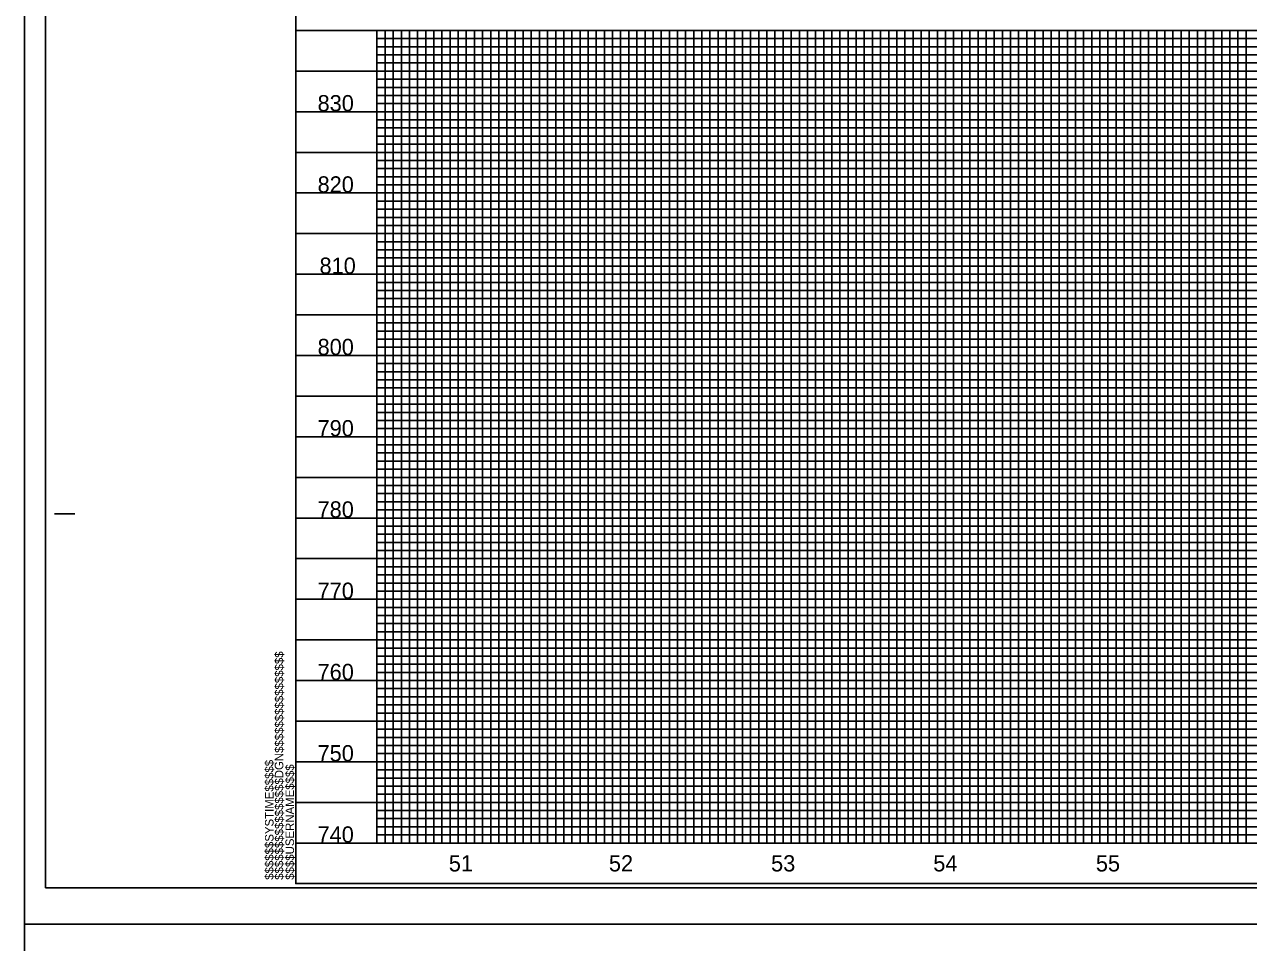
# Model space of a CAD drawing. Extents: x 1755181 to 1757273, y 729911 to 735411.
# Drawn here: x 1755181 to 1755934, y 733200 to 733764 of the extents above; entities that cross this region are included whole.
import ezdxf

# ---------------------------------------------------------------- set-up
doc = ezdxf.new("R2010")
doc.units = 0
for name, color, linetype in [('Exist Vertical Profile Horizontal Axis Label Major', 7, 'Continuous'), ('Exist Vertical Profile Vertical Axis Label', 7, 'Continuous'), ('Scratch_Level_3', 7, 'Continuous'), ('Sheet Cutting Line CELL', 7, 'Continuous'), ('Sheet DOT Grid CELL', 7, 'Continuous'), ('Sheet Plot Border Inside CELL', 7, 'Continuous'), ('Sheet Plot Border Outside CELL', 7, 'Continuous'), ('Sheet Profile CELL', 7, 'Continuous'), ('Sheet Profile Grid Major CELL', 7, 'Continuous'), ('Sheet Profile Grid Middle CELL', 7, 'Continuous'), ('Sheet Profile Grid Minor CELL', 7, 'Continuous')]:
    doc.layers.add(name, color=color, linetype=linetype)

msp = doc.modelspace()

# ---------------------------------------------------------------- linework, layer by layer
at = {"layer": 'Scratch_Level_3'}
msp.add_lwpolyline([(1755397.67, 733760.78), (1756847.67, 733760.78), (1756847.67, 733260.78), (1755397.67, 733260.78)], close=True, dxfattribs=at)
at = {"layer": 'Sheet Cutting Line CELL'}
for p, q in [((1755180.67, 734310.78), (1755180.67, 733210.78)), ((1755180.67, 733210.78), (1756864.67, 733210.78)), ((1755180.67, 733210.78), (1755180.67, 732110.78))]:
    msp.add_line(p, q, dxfattribs=at)
at = {"layer": 'Sheet DOT Grid CELL'}
for p, q in [((1755347.67, 733760.78), (1756797.67, 733760.78)), ((1755397.67, 733760.78), (1755397.67, 733260.78)), ((1755447.67, 733760.78), (1755447.67, 733260.78)), ((1755497.67, 733760.78), (1755497.67, 733260.78)), ((1755547.67, 733760.78), (1755547.67, 733260.78)), ((1755597.67, 733760.78), (1755597.67, 733260.78)), ((1755647.67, 733760.78), (1755647.67, 733260.78)), ((1755697.67, 733760.78), (1755697.67, 733260.78)), ((1755747.67, 733760.78), (1755747.67, 733260.78)), ((1755797.67, 733760.78), (1755797.67, 733260.78)), ((1755847.67, 733760.78), (1755847.67, 733260.78)), ((1755897.67, 733760.78), (1755897.67, 733260.78)), ((1755347.67, 733710.78), (1756847.56, 733710.78)), ((1755347.67, 733660.78), (1756847.56, 733660.78)), ((1755347.67, 733610.78), (1756847.56, 733610.78)), ((1755347.67, 733560.78), (1756847.56, 733560.78)), ((1755347.67, 733510.78), (1756847.56, 733510.78)), ((1755347.67, 733460.78), (1756847.56, 733460.78)), ((1755347.67, 733410.78), (1756847.56, 733410.78)), ((1755347.67, 733360.78), (1756847.56, 733360.78)), ((1755347.67, 733310.78), (1756847.56, 733310.78))]:
    msp.add_line(p, q, dxfattribs=at)
at = {"layer": 'Sheet Plot Border Inside CELL'}
msp.add_lwpolyline([(1755193.67, 733233.23), (1756860.17, 733233.23), (1756860.17, 734288.33), (1755193.67, 734288.33)], close=True, dxfattribs=at)
at = {"layer": 'Sheet Plot Border Outside CELL'}
for points in [[(1755180.67, 733210.78), (1756864.67, 733210.78), (1756864.67, 734310.78), (1755180.67, 734310.78)], [(1755180.67, 732110.78), (1756864.67, 732110.78), (1756864.67, 733210.78), (1755180.67, 733210.78)]]:
    msp.add_lwpolyline(points, close=True, dxfattribs=at)
at = {"layer": 'Sheet Profile CELL'}
for p, q in [((1755347.67, 733760.78), (1756847.67, 733760.78)), ((1755199.17, 733463.28), (1755211.67, 733463.28)), ((1756847.67, 733260.78), (1755347.67, 733260.78)), ((1755347.67, 733235.78), (1756847.67, 733235.78)), ((1755347.67, 733235.78), (1755347.67, 733235.78))]:
    msp.add_line(p, q, dxfattribs=at)
msp.add_lwpolyline([(1756847.67, 734285.78), (1755347.67, 734285.78), (1755347.67, 733235.78), (1756847.67, 733235.78)], close=True, dxfattribs=at)
msp.add_lwpolyline([(1755385.17, 733235.78), (1755385.17, 733235.78)], dxfattribs=at)
at = {"layer": 'Sheet Profile Grid Major CELL'}
msp.add_line((1755847.67, 733760.78), (1755897.67, 733760.78), dxfattribs=at)
for points in [[(1755397.67, 733760.78), (1755397.67, 733260.78), (1755447.67, 733260.78), (1755447.67, 733760.78), (1755497.67, 733760.78), (1755497.67, 733260.78), (1755547.67, 733260.78), (1755547.67, 733760.78), (1755597.67, 733760.78), (1755597.67, 733260.78), (1755647.67, 733260.78), (1755647.67, 733760.78), (1755697.67, 733760.78), (1755697.67, 733260.78), (1755747.67, 733260.78), (1755747.67, 733760.78), (1755797.67, 733760.78), (1755797.67, 733260.78), (1755847.67, 733260.78), (1755847.67, 733760.78), (1755897.67, 733760.78), (1755897.67, 733260.78), (1755947.67, 733260.78)], [(1756847.67, 733710.78), (1755347.67, 733710.78)], [(1756847.67, 733660.78), (1755347.67, 733660.78), (1755347.67, 733610.78), (1756847.67, 733610.78)], [(1756847.67, 733560.78), (1755347.67, 733560.78), (1755347.67, 733510.78), (1756847.67, 733510.78)], [(1756847.67, 733460.78), (1755347.67, 733460.78), (1755347.67, 733410.78), (1756847.67, 733410.78)], [(1756847.67, 733360.78), (1755347.67, 733360.78), (1755347.67, 733360.78), (1755347.67, 733310.78), (1756847.67, 733310.78)], [(1756847.67, 733260.78), (1755347.67, 733260.78)]]:
    msp.add_lwpolyline(points, dxfattribs=at)
at = {"layer": 'Sheet Profile Grid Middle CELL'}
for points in [[(1755372.67, 733760.78), (1755422.67, 733760.78), (1755422.67, 733260.78), (1755472.67, 733260.78), (1755472.67, 733760.78), (1755522.67, 733760.78), (1755522.67, 733260.78), (1755572.67, 733260.78), (1755572.67, 733760.78), (1755622.67, 733760.78), (1755622.67, 733260.78), (1755672.67, 733260.78), (1755672.67, 733760.78), (1755722.67, 733760.78), (1755722.67, 733260.78), (1755772.67, 733260.78), (1755772.67, 733760.78), (1755822.67, 733760.78), (1755822.67, 733260.78), (1755872.67, 733260.78), (1755872.67, 733760.78), (1755922.67, 733760.78), (1755922.67, 733260.78), (1755972.67, 733260.78)], [(1755347.67, 733735.78), (1756097.67, 733735.78)], [(1756097.67, 733685.78), (1755347.67, 733685.78), (1755347.67, 733635.78), (1756097.67, 733635.78)], [(1756097.67, 733585.78), (1755347.67, 733585.78), (1755347.67, 733535.78), (1756097.67, 733535.78)], [(1756097.67, 733485.78), (1755347.67, 733485.78), (1755347.67, 733435.78), (1756097.67, 733435.78)], [(1756097.67, 733385.78), (1755347.67, 733385.78), (1755347.67, 733335.78), (1756097.67, 733335.78)], [(1756097.67, 733285.78), (1755347.67, 733285.78)]]:
    msp.add_lwpolyline(points, dxfattribs=at)
at = {"layer": 'Sheet Profile Grid Minor CELL'}
for p, q in [((1755397.67, 733755.78), (1756102.67, 733755.78)), ((1756102.67, 733750.78), (1755397.67, 733750.78)), ((1755397.67, 733745.78), (1756102.67, 733745.78)), ((1756102.67, 733740.78), (1755397.67, 733740.78)), ((1755397.67, 733730.78), (1756102.67, 733730.78)), ((1756102.67, 733725.78), (1755397.67, 733725.78)), ((1755397.67, 733720.78), (1756102.67, 733720.78)), ((1756102.67, 733715.78), (1755397.67, 733715.78)), ((1755397.67, 733705.78), (1756102.67, 733705.78)), ((1756102.67, 733700.78), (1755397.67, 733700.78)), ((1755397.67, 733695.78), (1756102.67, 733695.78)), ((1756102.67, 733690.78), (1755397.67, 733690.78)), ((1755397.67, 733680.78), (1756102.67, 733680.78)), ((1756102.67, 733675.78), (1755397.67, 733675.78)), ((1755397.67, 733670.78), (1756102.67, 733670.78)), ((1756102.67, 733665.78), (1755397.67, 733665.78)), ((1755397.67, 733655.78), (1756102.67, 733655.78)), ((1756102.67, 733650.78), (1755397.67, 733650.78)), ((1755397.67, 733645.78), (1756102.67, 733645.78)), ((1756102.67, 733640.78), (1755397.67, 733640.78)), ((1755397.67, 733630.78), (1756102.67, 733630.78)), ((1756102.67, 733625.78), (1755397.67, 733625.78)), ((1755397.67, 733620.78), (1756102.67, 733620.78)), ((1756102.67, 733615.78), (1755397.67, 733615.78)), ((1755397.67, 733605.78), (1756102.67, 733605.78)), ((1756102.67, 733600.78), (1755397.67, 733600.78)), ((1755397.67, 733595.78), (1756102.67, 733595.78)), ((1756102.67, 733590.78), (1755397.67, 733590.78)), ((1755397.67, 733580.78), (1756102.67, 733580.78)), ((1756102.67, 733575.78), (1755397.67, 733575.78)), ((1755397.67, 733570.78), (1756102.67, 733570.78)), ((1756102.67, 733565.86), (1755397.67, 733565.93)), ((1755397.67, 733555.78), (1756102.67, 733555.78)), ((1756102.67, 733550.78), (1755397.67, 733550.78)), ((1755397.67, 733545.78), (1756102.67, 733545.78)), ((1756102.67, 733540.78), (1755397.67, 733540.78)), ((1755397.67, 733530.78), (1756102.67, 733530.78)), ((1756102.67, 733525.78), (1755397.67, 733525.78)), ((1755397.67, 733520.78), (1756102.67, 733520.78)), ((1756102.67, 733515.78), (1755397.67, 733515.78)), ((1755397.67, 733505.78), (1756102.67, 733505.78)), ((1756102.67, 733500.78), (1755397.67, 733500.78)), ((1755397.67, 733495.78), (1756102.67, 733495.78)), ((1756102.67, 733490.78), (1755397.67, 733490.78)), ((1755397.67, 733480.78), (1756102.67, 733480.78)), ((1756102.67, 733475.78), (1755397.67, 733475.78)), ((1755397.67, 733470.78), (1756102.67, 733470.78)), ((1756102.67, 733465.78), (1755397.67, 733465.78)), ((1755397.67, 733455.78), (1756102.67, 733455.78)), ((1756102.67, 733450.78), (1755397.67, 733450.78)), ((1755397.67, 733445.78), (1756102.67, 733445.78)), ((1756102.67, 733440.78), (1755397.67, 733440.78)), ((1755397.67, 733430.78), (1756102.67, 733430.78)), ((1756102.67, 733425.78), (1755397.67, 733425.78)), ((1755397.67, 733420.78), (1756102.67, 733420.78)), ((1756102.67, 733415.78), (1755397.67, 733415.78)), ((1755397.67, 733405.78), (1756102.67, 733405.78)), ((1756102.67, 733400.78), (1755397.67, 733400.78)), ((1755397.67, 733395.78), (1756102.67, 733395.78)), ((1756102.67, 733390.78), (1755397.67, 733390.78)), ((1755397.67, 733380.78), (1756102.67, 733380.78)), ((1756102.67, 733375.78), (1755397.67, 733375.78)), ((1755397.67, 733370.78), (1756102.67, 733370.78)), ((1756102.67, 733365.78), (1755397.67, 733365.78)), ((1755397.67, 733355.78), (1756102.67, 733355.78)), ((1756102.67, 733350.78), (1755397.67, 733350.78)), ((1755397.67, 733345.78), (1756102.67, 733345.78)), ((1756102.67, 733340.78), (1755397.67, 733340.78)), ((1755397.67, 733330.78), (1756102.67, 733330.78)), ((1756102.67, 733325.78), (1755397.67, 733325.78)), ((1755397.67, 733320.78), (1756102.67, 733320.78)), ((1756102.67, 733315.78), (1755397.67, 733315.78)), ((1755397.67, 733305.78), (1756102.67, 733305.78)), ((1756102.67, 733300.78), (1755397.67, 733300.78)), ((1755397.67, 733295.78), (1756102.67, 733295.78)), ((1756102.67, 733290.78), (1755397.67, 733290.78)), ((1755397.67, 733280.78), (1756102.67, 733280.78)), ((1756102.67, 733275.78), (1755397.67, 733275.78)), ((1755397.67, 733270.78), (1756102.67, 733270.78)), ((1755397.67, 733265.78), (1756102.67, 733265.78))]:
    msp.add_line(p, q, dxfattribs=at)
for points in [[(1755397.67, 733760.78), (1755402.67, 733760.78), (1755402.67, 733260.78), (1755407.67, 733260.78), (1755407.67, 733760.78), (1755412.67, 733760.78), (1755412.67, 733260.78), (1755417.67, 733260.78), (1755417.67, 733760.78), (1755427.67, 733760.78), (1755427.67, 733260.78), (1755432.67, 733260.78), (1755432.67, 733760.78), (1755437.67, 733760.78), (1755437.67, 733260.78), (1755442.67, 733260.78), (1755452.67, 733260.78), (1755457.67, 733260.78), (1755457.67, 733760.78), (1755462.67, 733760.78), (1755462.67, 733260.78), (1755467.67, 733260.78), (1755467.67, 733760.78), (1755477.67, 733760.78), (1755477.67, 733260.78), (1755482.67, 733260.78), (1755482.67, 733760.78), (1755487.67, 733760.78), (1755487.67, 733260.78), (1755492.67, 733260.78), (1755492.67, 733760.78), (1755502.67, 733760.78), (1755502.67, 733260.78), (1755507.67, 733260.78), (1755507.67, 733760.78), (1755512.67, 733760.78), (1755512.67, 733260.78), (1755517.67, 733260.78), (1755517.67, 733760.78), (1755527.67, 733760.78), (1755527.67, 733260.78), (1755532.67, 733260.78), (1755532.67, 733760.78), (1755537.67, 733760.78), (1755537.67, 733260.78), (1755542.67, 733260.78), (1755542.67, 733760.78), (1755552.67, 733760.78), (1755552.67, 733260.78), (1755557.67, 733260.78), (1755557.67, 733760.78), (1755562.67, 733760.78), (1755562.67, 733260.78), (1755567.67, 733260.78), (1755567.67, 733760.78), (1755577.67, 733760.78), (1755577.67, 733260.78), (1755582.67, 733260.78), (1755582.67, 733760.78), (1755587.67, 733760.78), (1755587.67, 733260.78), (1755592.67, 733260.78), (1755592.67, 733760.78), (1755602.67, 733760.78), (1755602.67, 733260.78), (1755607.67, 733260.78), (1755607.67, 733760.78), (1755612.67, 733760.78), (1755612.67, 733260.78)], [(1755442.67, 733260.78), (1755442.67, 733760.78), (1755452.67, 733760.78), (1755452.67, 733260.78)], [(1755612.67, 733260.78), (1755617.67, 733260.78), (1755617.67, 733760.78), (1755627.67, 733760.78), (1755627.67, 733260.78), (1755632.67, 733260.78), (1755632.67, 733760.78), (1755637.67, 733760.78), (1755637.67, 733260.78), (1755642.67, 733260.78), (1755642.67, 733760.78), (1755652.67, 733760.78), (1755652.67, 733260.78), (1755657.67, 733260.78), (1755657.67, 733760.78), (1755662.67, 733760.78), (1755662.67, 733260.78), (1755667.67, 733260.78), (1755667.67, 733760.78), (1755677.67, 733760.78), (1755677.67, 733260.78), (1755682.67, 733260.78), (1755682.67, 733760.78), (1755687.67, 733760.78), (1755687.67, 733260.78), (1755692.67, 733260.78), (1755692.67, 733760.78), (1755702.67, 733760.78), (1755702.67, 733260.78), (1755707.67, 733260.78), (1755707.67, 733760.78), (1755712.67, 733760.78), (1755712.67, 733260.78), (1755717.67, 733260.78), (1755717.67, 733760.78), (1755727.67, 733760.78), (1755727.67, 733260.78), (1755732.67, 733260.78), (1755732.67, 733760.78), (1755737.67, 733760.78), (1755737.67, 733260.78), (1755742.67, 733260.78), (1755742.67, 733760.78), (1755752.67, 733760.78), (1755752.67, 733260.78), (1755757.67, 733260.78), (1755757.67, 733760.78), (1755762.67, 733760.78), (1755762.67, 733260.78), (1755767.67, 733260.78), (1755767.67, 733760.78), (1755777.67, 733760.78), (1755777.67, 733260.78), (1755782.67, 733260.78), (1755782.67, 733760.78), (1755787.67, 733760.78), (1755787.67, 733260.78), (1755792.67, 733260.78), (1755792.67, 733760.78), (1755802.67, 733760.78), (1755802.67, 733260.78), (1755807.67, 733260.78), (1755807.67, 733760.78), (1755812.67, 733760.78), (1755812.67, 733260.78), (1755817.67, 733260.78), (1755817.67, 733760.78), (1755827.67, 733760.78), (1755827.67, 733260.78), (1755832.67, 733260.78), (1755832.67, 733760.78), (1755837.67, 733760.78), (1755837.67, 733260.78), (1755842.67, 733260.78), (1755842.67, 733760.78), (1755852.67, 733760.78), (1755852.67, 733260.78), (1755857.67, 733260.78), (1755857.67, 733760.78), (1755862.67, 733760.78), (1755862.67, 733260.78), (1755867.67, 733260.78), (1755867.67, 733760.78), (1755877.67, 733760.78), (1755877.67, 733260.78), (1755882.67, 733260.78), (1755882.67, 733760.78), (1755887.67, 733760.78), (1755887.67, 733260.78), (1755892.67, 733260.78), (1755892.67, 733760.78), (1755902.67, 733760.78), (1755902.67, 733260.78), (1755907.67, 733260.78), (1755907.67, 733760.78), (1755912.67, 733760.78), (1755912.67, 733260.78), (1755917.67, 733260.78), (1755917.67, 733760.78), (1755927.67, 733760.78)], [(1755927.67, 733760.78), (1755927.67, 733260.78), (1755932.67, 733260.78), (1755932.67, 733760.78), (1755937.67, 733760.78)]]:
    msp.add_lwpolyline(points, dxfattribs=at)

# ---------------------------------------------------------------- texts
at = {"layer": 'Exist Vertical Profile Horizontal Axis Label Major'}
for s, p in [('51', (1755441.89, 733243.28)), ('52', (1755540.44, 733243.28)), ('53', (1755640.28, 733243.28)), ('54', (1755740.12, 733243.28)), ('55', (1755840.21, 733243.28))]:
    msp.add_text(s, height=10, dxfattribs=at).set_placement(p)
at = {"layer": 'Exist Vertical Profile Vertical Axis Label'}
for s, p in [('830', (1755361.1, 733711.03)), ('820', (1755361.1, 733661.03)), ('810', (1755362.3, 733611.03)), ('800', (1755361.1, 733561.03)), ('790', (1755361.1, 733511.03)), ('780', (1755361.1, 733461.03)), ('770', (1755361.1, 733411.03)), ('760', (1755361.1, 733361.03)), ('750', (1755361.1, 733311.03)), ('740', (1755361.1, 733261.03))]:
    msp.add_text(s, height=10, dxfattribs=at).set_placement(p)
at = {"layer": 'Sheet Profile CELL'}
for s, p in [('$$$$$$$$$$$$$$$$DGN$$$$$$$$$$$$$$$$', (1755340.03, 733238.16)), ('$$$$$$SYSTIME$$$$$', (1755333.98, 733238.16)), ('$$$$USERNAME$$$$', (1755346.61, 733238.17))]:
    msp.add_text(s, height=5.25, rotation=90, dxfattribs=at).set_placement(p)

doc.saveas('drawing.dxf')
